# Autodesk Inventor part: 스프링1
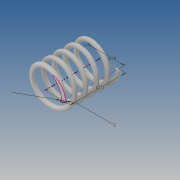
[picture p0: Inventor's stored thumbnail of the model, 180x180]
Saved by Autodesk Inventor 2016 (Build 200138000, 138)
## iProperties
Created: 2016-10
Part Number: 스프링1
Material: Generic
Document SubType Name: Modeling
Designer: Administrator
Density: 1 g/cm^3
Appearance: Default
Mass: 0.874294 g
Surface Area: 17.7466 cm^2
Volume: 0.874294 cm^3
Author: Administrator
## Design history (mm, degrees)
sketch "스케치1"
  geometry: L1 (0, 0)-(-9, 0); L2 (-9, 0)-(-9, -27); L3 (-9, -27)-(0, -27); L4 (0, -27)-(0, 0); C1 r 1 at (-9, 0)
  constraints: 8 end point, 2 parallel, 1 centre point, 1 coincident, 1 horizontal, 1 perpendicular
  dimensions: "d0" = 2 diameter of C1; "d1" = 27 distance of L1.end L2.end (derived); "d2" = 18 diameter of L2 L4
feature "코일1" pitch "d3" = 10; turns "d5" = 5; dims "d4" = 27 (= d1), "d6" = 0, angle "d7" = 90 deg, angle "d8" = 90 deg, "d9" = 0, "d10" = 0
sketch "스케치2"
  geometry: L1 (10, 0)-(8, 0) reference; 1 further point
  constraints: 1 horizontal alignment
  node "절단 모서리 투영1"
extrude "돌출1" cut sketch "스케치2" stored distance "d11" = 10; taper "d12" = 0 deg
node "작업 평면3"
sketch "스케치3"
  geometry: L1 (-1, 0)-(1, 0) reference; 1 further point
  constraints: 1 horizontal alignment
extrude "돌출2" cut sketch "스케치3" stored distance "d14" = 0; taper "d15" = 0 deg
node "솔리드1"
node "절단 모서리 투영2"
other parameters: "d13" = 90 deg
